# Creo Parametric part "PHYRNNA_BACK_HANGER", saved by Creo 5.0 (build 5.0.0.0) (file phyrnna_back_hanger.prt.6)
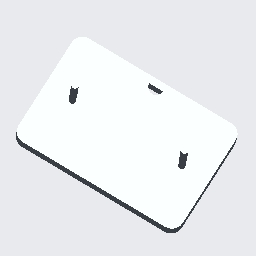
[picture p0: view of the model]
Units: Inch lbm Second (Pro/E Default); INCH, POUND, SECS

Created from: INLBS_PART_SOLID.PRT

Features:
  1. datum plane "RIGHT"
  2. datum plane "TOP"
  3. datum plane "FRONT"
  4. coordinate system
  5. sketch "Sketch 1"
  6. extrusion "Extrude 1"
  7. sketch "Sketch 2"
  8. extrusion "Extrude 2"
  9. sketch "Sketch 1"
  10. extruded cut "Extrude 1"

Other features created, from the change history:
  sketch "Sketch 1" (2 times)
  extruded cut "Extrude 1"
  chamfer "Chamfer 1"
  sketch "Sketch 2"
  extruded cut "Extrude 2"
  extrusion "Extrude 1"

Other named items: BASE_S, BASE_E, PEG_S, PEG_E, LOOP_S, LOOP_E

Surfaces: 8 plane, 7 cylinder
